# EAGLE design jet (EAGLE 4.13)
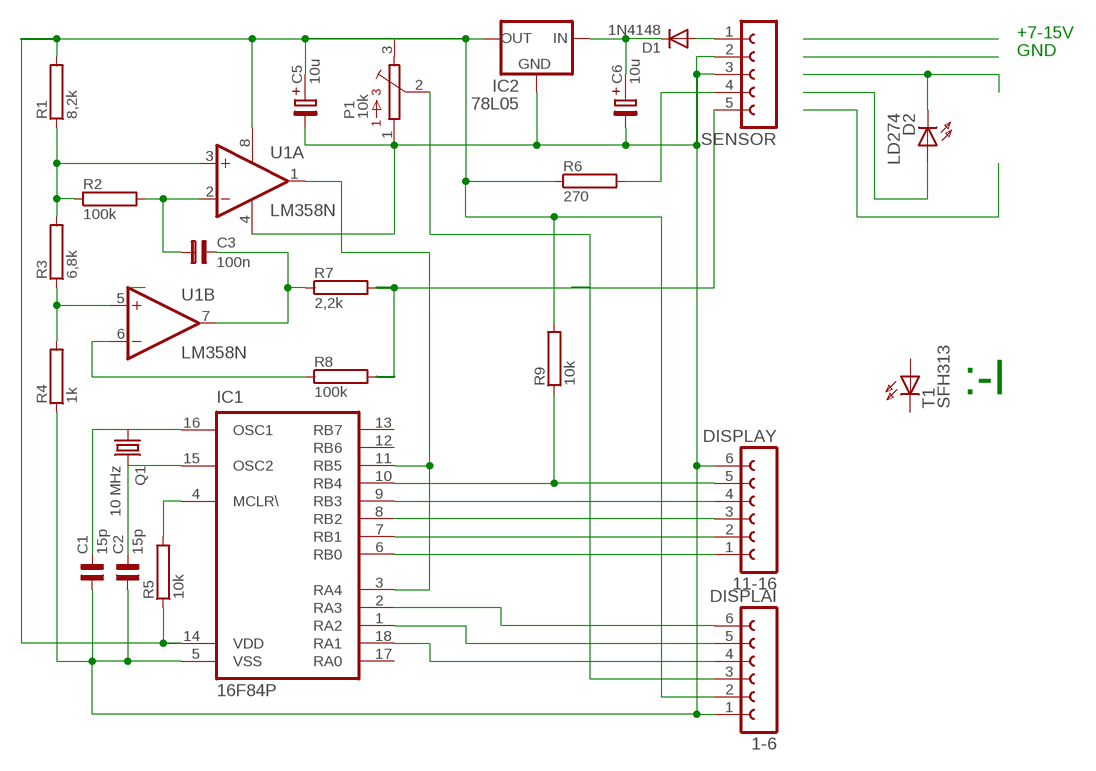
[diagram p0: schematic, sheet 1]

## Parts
C1  15p  C5E  [C5B2,5]
C2  15p  C5E  [C5B2,5]
C3  100n  C5E  [C5B2,5]
C5  10u  TT2D5  [TT2D5]
C6  10u  TT2D5  [TT2D5]
D1  1N4148  [RAD2,5]
D2  LD274  LED5MM  [LED5MM]
DISPLAI  1-6  FE06-1  [MA06-1]
DISPLAY  11-16  FE06-1  [MA06-1]
IC1  16F84P  [DIL18]
IC2  78L05  78LXX  [78LXX]
P1  10k  RJ6  [B64W]
Q1  10 MHz  HC18U-H  [HC18U-H]
R1  8,2k  0204/7  [0204/7]
R2  100k  0204/7  [0204/7]
R3  6,8k  0204/7  [0204/7]
R4  1k  0204/7  [0204/7]
R5  10k  0204/7  [0204/7]
R6  270  0204/7@2  [0207/7]
R7  2,2k  0204/7  [0204/7]
R8  100k  0204/7  [0204/7]
R9  10k  0207/10  [0207/10]
SENSOR  FE05-1  [MA05-1]
T1  SFH313  LED5MM  [LED5MM]
U1  LM358N  [DIL08]

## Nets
11: R1.1 R2.1 R3.2 U1.3(A:+IN)
GND: C1.1 C2.1 C5.- C6.- DISPLAI.1 DISPLAY.6 IC1.5(VSS) IC2.GND P1.1 R4.1 SENSOR.2 SENSOR.3 U1.4(P:V-)
N$1: D1.A SENSOR.1
N$2: C1.2 IC1.16(OSC1) Q1.1
N$3: C2.2 IC1.15(OSC2) Q1.2
N$4: DISPLAY.1 IC1.6(RB0)
N$5: DISPLAY.2 IC1.7(RB1)
N$6: IC1.4(MCLR\) R5.2
N$7: R8.1 U1.6(B:-IN)
N$8: DISPLAY.3 IC1.8(RB2)
N$9: DISPLAY.4 IC1.9(RB3)
N$10: R6.2 SENSOR.4
N$11: D2.K(C)
N$14: DISPLAI.5 IC1.1(RA2)
N$15: DISPLAI.6 IC1.2(RA3)
N$16: DISPLAI.4 IC1.18(RA1)
N$17: IC1.3(RA4) IC1.11(RB5) U1.1(A:OUT)
N$18: R3.1 R4.2 U1.5(B:+IN)
N$19: D2.A
N$20: DISPLAY.5 IC1.10(RB4) R9.1
N$21: C3.1 R2.2 U1.2(A:-IN)
N$22: C6.+ D1.K IC2.IN
N$23: C3.2 R7.1 U1.7(B:OUT)
N$24: R7.2 R8.2 SENSOR.5
N$26: DISPLAI.3 P1.2
V+: C5.+ DISPLAI.2 IC1.14(VDD) IC2.OUT P1.3 R1.2 R5.1 R6.1 R9.2 U1.8(P:V+)
Unconnected: IC1.12(RB6) IC1.13(RB7) IC1.17(RA0) T1.A T1.K(C)

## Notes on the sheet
- +7-15V
- GND
- :-I

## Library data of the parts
C1-C3 = CAP:C5E
C5 C6 = CAP-TANT:TT2D5
D1 = DIODE:1N4148
D2 T1 = led:LED5MM: LED
DISPLAI DISPLAY = CON-LSTA:FE06-1
IC1 = PIC:16F84P
IC2 = V-REG:78LXX
P1 = TRIMPOT:RJ6
Q1 = QUARTZ:HC18U-H
R1-R5 R7 R8 = R:0204/7
R6 = R:0204/7@2
R9 = R:0207/10
SENSOR = CON-LSTA:FE05-1
U1 = LINEAR:LM358N

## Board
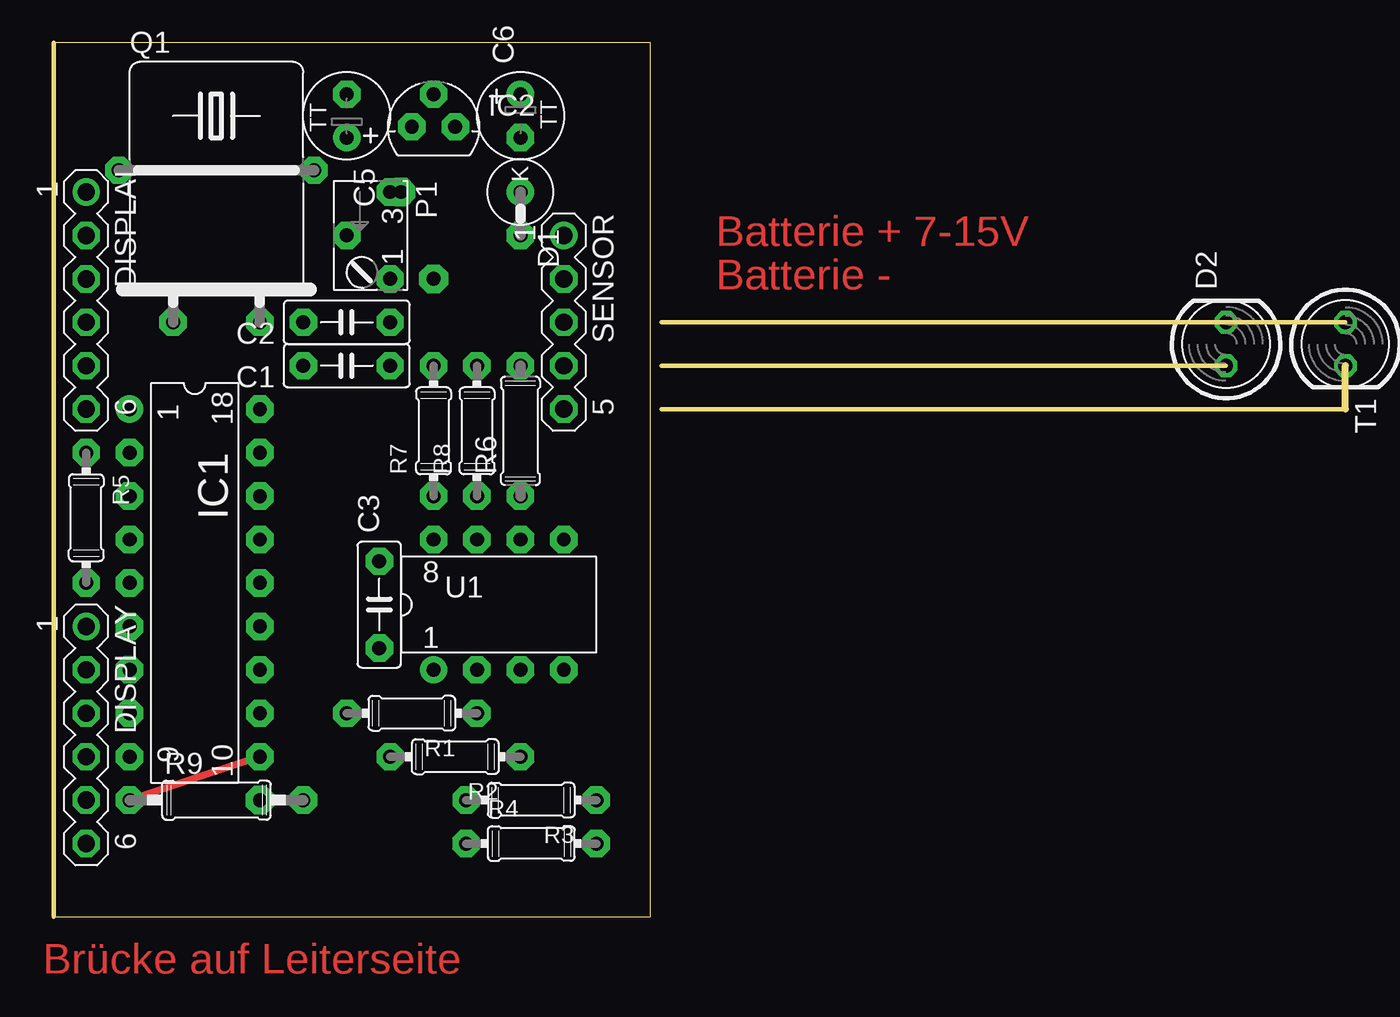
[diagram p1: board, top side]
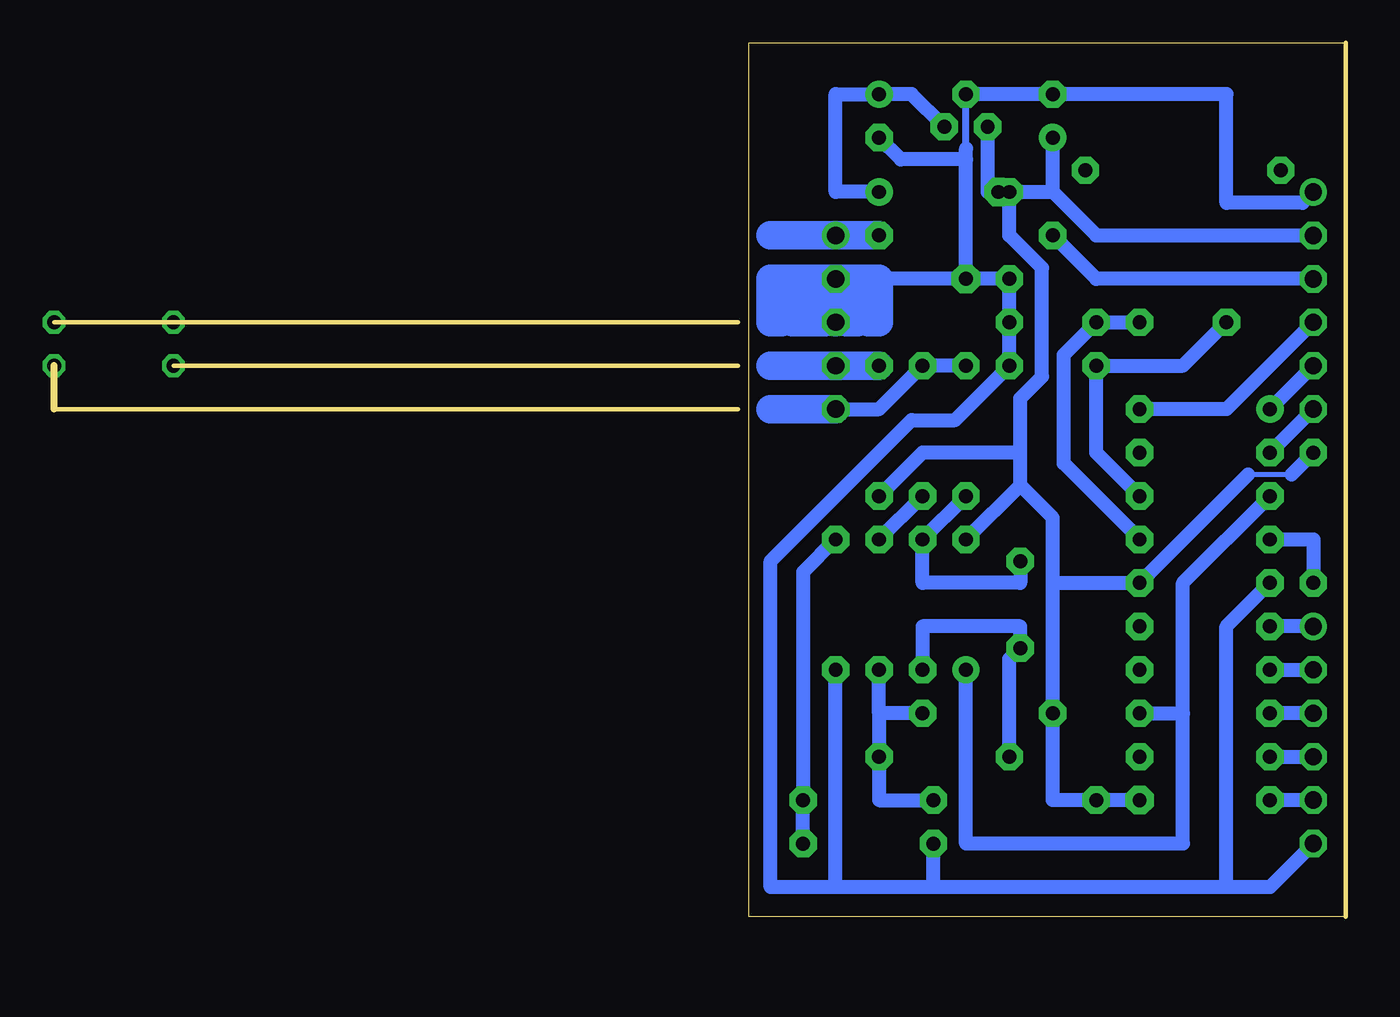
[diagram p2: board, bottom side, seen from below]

Size 75.56 x 51.11 mm. Coordinates in mm from the lower left corner, seen from the top.
Outline: 35.55,34.76 75.56,34.76
Outline: 35.55,32.22 68.57,32.22
Outline: 35.55,29.68 75.56,29.68 75.56,32.22
Outline: 0,0 34.91,0 34.91,51.11 0,51.11 0,0
Copper layers (1*16): Top 0.035mm / dielectric 1.5mm / Bottom 0.035mm
Design rules "default": minimum track width 10mil, minimum drill 24mil, track to track 8mil, track to pad 8mil, pad to pad 8mil, via to via 8mil, smd to smd 8mil, copper to edge 40mil, drill to drill 8mil, minimum pad ring 10mil, minimum via ring 8mil, stop-mask expansion 0mil, vias tented up to drill 0mil, thermal gap 10mil

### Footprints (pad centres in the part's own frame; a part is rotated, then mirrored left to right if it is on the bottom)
C5B2,5 = drill 0.813 pad 1.6 octagon: 1 -2.54,0; 2 2.54,0
TT2D5 = drill 0.813 pad 1.6 round: + 1.27,0 | drill 0.813 pad 1.6 octagon: - -1.27,0
RAD2,5 = drill 0.813 pad 1.6 octagon: A 1.27,0 | drill 0.813 pad 1.6 round: K -1.27,0
LED5MM = drill 0.813 octagon: A -1.27,0; K 1.27,0
MA06-1 = drill 1.016 pad 1.6 round: 1 -6.35,0 | drill 1.016 pad 1.6 octagon: 2 -3.81,0; 3 -1.27,0; 4 1.27,0; 5 3.81,0; 6 6.35,0
DIL18 = drill 0.813 pad 1.6 round: 1 -10.16,-3.81 | drill 0.813 pad 1.6 octagon: 2 -7.62,-3.81; 3 -5.08,-3.81; 4 -2.54,-3.81; 5 0,-3.81; 6 2.54,-3.81; 7 5.08,-3.81; 8 7.62,-3.81; 9 10.16,-3.81; 10 10.16,3.81; 11 7.62,3.81; 12 5.08,3.81; 13 2.54,3.81; 14 0,3.81; 15 -2.54,3.81; 16 -5.08,3.81; 17 -7.62,3.81; 18 -10.16,3.81
78LXX = drill 0.813 pad 1.6 octagon: GND 0,1.905; IN 1.27,0; OUT -1.27,0
B64W = drill 0.813 pad 1.6 octagon: 1 2.54,0; 2 0,-2.54; 3 -2.54,0
HC18U-H = drill 0.813 pad 1.6 octagon: 1 -2.54,-5.08; 2 2.54,-5.08; M -5.715,3.81; M1 5.715,3.81
0204/7 = drill 0.813 pad 1.6 octagon: 1 -3.81,0; 2 3.81,0
0207/7 = drill 0.813 pad 1.6 octagon: 1 -3.81,0; 2 3.81,0
0207/10 = drill 0.813 pad 1.6 octagon: 1 -5.08,0; 2 5.08,0
MA05-1 = drill 1.016 pad 1.6 round: 1 -5.08,0 | drill 1.016 pad 1.6 octagon: 2 -2.54,0; 3 0,0; 4 2.54,0; 5 5.08,0
DIL08 = drill 0.813 pad 1.6 round: 1 -3.81,-3.81 | drill 0.813 pad 1.6 octagon: 2 -1.27,-3.81; 3 1.27,-3.81; 4 3.81,-3.81; 5 3.81,3.81; 6 1.27,3.81; 7 -1.27,3.81; 8 -3.81,3.81

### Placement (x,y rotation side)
C1  17.14,32.22 180 top
C2  17.14,34.76 180 top
C3  19.05,18.25 90 top
C5  17.14,46.83 270 top
C6  27.3,46.83 90 top
D1  27.3,41.11 270 top
D2  68.57,33.49 90 top
DISPLAI  1.9,36.03 270 top
DISPLAY  1.9,10.63 270 top
IC1  8.25,19.52 270 top
IC2  22.22,46.19 0 top
P1  19.68,39.84 270 top
Q1  9.52,39.84 0 top
R1  20.95,11.9 180 top
R2  23.49,9.36 180 top
R3  27.93,6.82 180 top
R4  27.93,4.28 0 top
R5  1.9,23.33 270 top
R6  27.3,28.41 90 top
R7  22.22,28.41 90 top
R8  24.76,28.41 90 top
R9  9.52,6.82 0 top
SENSOR  29.84,34.76 270 top
T1  75.56,33.49 270 top
U1  26.03,18.25 0 top

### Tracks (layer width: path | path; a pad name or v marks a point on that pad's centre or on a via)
11
  Bottom 0.305: 27.3,11.9 R2.1
  Bottom 0.813: 27.3,11.9 U1.3 | R1.1 27.3,11.9 | 27.3,11.9 27.3,6.82 R3.2
GND  (via drill 0.81 pad 1.68)
  Bottom 0.254: 4.44,1.74 6.98,1.74 24.12,1.74 | C1.1 C2.1 | C1.1 C2.1 | C1.1 C2.1 | C1.1 C2.1 | C1.1 C2.1 | C1.1 C2.1
  Bottom 0.305: 33.02,34.76 30.48,37.3 v22.22,37.3 P1.1 C1.1
  Bottom 0.406: 22.22,44.92 IC2.GND
  Bottom 0.813: IC1.5 6.98,16.98 6.98,1.74 | DISPLAY.6 4.44,1.74 24.12,1.74 | v22.22,37.3 22.22,44.29 | 22.22,44.29 22.22,44.92 | v22.22,37.3 27.3,37.3 | v22.22,37.3 P1.1 C2.1 C1.1 22.86,29.04 25.39,29.04 33.65,20.79 33.65,1.74 29.84,1.74 | C6.- 26.03,44.29 22.22,44.29 | DISPLAI.1 2.53,41.75 6.98,41.75 6.98,48.1 C5.- IC2.GND | 24.12,1.74 R4.1 | 24.12,1.74 29.84,1.74 | 29.84,1.74 U1.4
  Bottom 1.676: 30.48,37.3 31.74,37.3 | 33.02,37.3 33.65,37.3 33.65,34.76 33.02,34.76 33.02,37.3 | 31.74,37.3 33.02,37.3 | 31.74,37.3 31.74,34.76 | 31.74,34.76 32.38,34.76 | 31.74,34.76 30.48,34.76 30.48,37.3 | SENSOR.2 30.48,37.3 | 28.57,37.3 29.2,37.3 | 27.93,37.3 27.3,37.3 27.3,34.76 27.93,34.76 27.93,37.3 | 27.93,37.3 28.57,37.3 | 28.57,37.3 28.57,34.76 29.2,34.76 29.2,37.3 | 29.2,37.3 SENSOR.2 | SENSOR.2 SENSOR.3
N$1
  Bottom 1.676: D1.A SENSOR.1 33.65,39.84
N$2
  Bottom 0.813: IC1.16 14.6,27.14 C1.2 9.52,32.22 Q1.1
N$3
  Bottom 0.813: IC1.15 16.5,26.5 16.5,32.86 C2.2 Q1.2
N$4
  Bottom 0.813: DISPLAY.1 IC1.6
N$5
  Bottom 0.813: IC1.7 DISPLAY.2
N$6
  Bottom 0.813: IC1.4 1.9,22.06 R5.2
N$7
  Bottom 0.813: U1.6 R8.1
N$8
  Bottom 0.813: DISPLAY.3 IC1.8
N$9
  Bottom 0.813: IC1.9 DISPLAY.4
N$10
  Bottom 1.676: R6.2 SENSOR.4 33.65,32.22
N$13  (via drill 0.81 pad 1.68)
  other vias: 12.06,6.82
N$14
  Bottom 0.813: DISPLAI.5 IC1.1
N$15
  Bottom 0.813: DISPLAI.6 IC1.2
N$16
  Bottom 0.813: DISPLAI.4 6.98,29.68 IC1.18
N$17
  Bottom 0.813: U1.1 22.22,4.28 9.52,4.28 9.52,11.9 | IC1.11 9.52,11.9 | 9.52,11.9 9.52,19.52 IC1.3
N$18
  Bottom 0.813: U1.5 31.74,20.15 R3.1 R4.2
N$20
  Top 0.406: IC1.10 R9.1
  Bottom 0.813: DISPLAY.5 R9.1
N$21
  Bottom 0.813: U1.2 24.76,16.98 19.05,16.98 C3.1 19.68,15.07 R2.2
N$22
  Bottom 0.813: D1.K 29.84,42.38 29.84,48.1 C6.+ 25.39,48.1 IC2.IN
N$23
  Bottom 0.813: R7.1 U1.7 24.76,19.52 19.05,19.52 C3.2
N$24
  Bottom 0.813: R7.2 R8.2 27.3,29.68 SENSOR.5
  Bottom 1.676: SENSOR.5 33.65,29.68
N$26
  Bottom 0.813: DISPLAI.3 14.6,37.3 P1.2
V+  (via drill 0.81 pad 1.68)
  Bottom 0.305: 5.71,25.87 3.17,25.87
  Bottom 0.406: 17.14,19.52 17.14,6.82 12.06,6.82
  Bottom 0.813: R6.1 24.76,27.14 19.05,27.14 | DISPLAI.2 14.6,39.84 17.14,42.38 | 19.05,27.14 19.05,30.32 17.77,31.58 17.77,37.94 19.68,39.84 P1.3 | 19.05,25.23 19.05,27.14 | 19.05,25.23 17.14,23.33 17.14,19.52 | 19.05,25.23 U1.8 | 5.71,25.87 IC1.14 17.14,19.52 | 3.17,25.87 R5.1 | 17.14,42.38 C5.+ | P1.3 17.14,42.38 | P1.3 v20.32,42.38 20.95,42.38 IC2.OUT | 17.14,19.52 R1.2 17.14,6.82 R9.2 12.06,6.82

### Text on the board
Top: Batterie + 7-15V | Batterie - | Brücke auf Leiterseite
